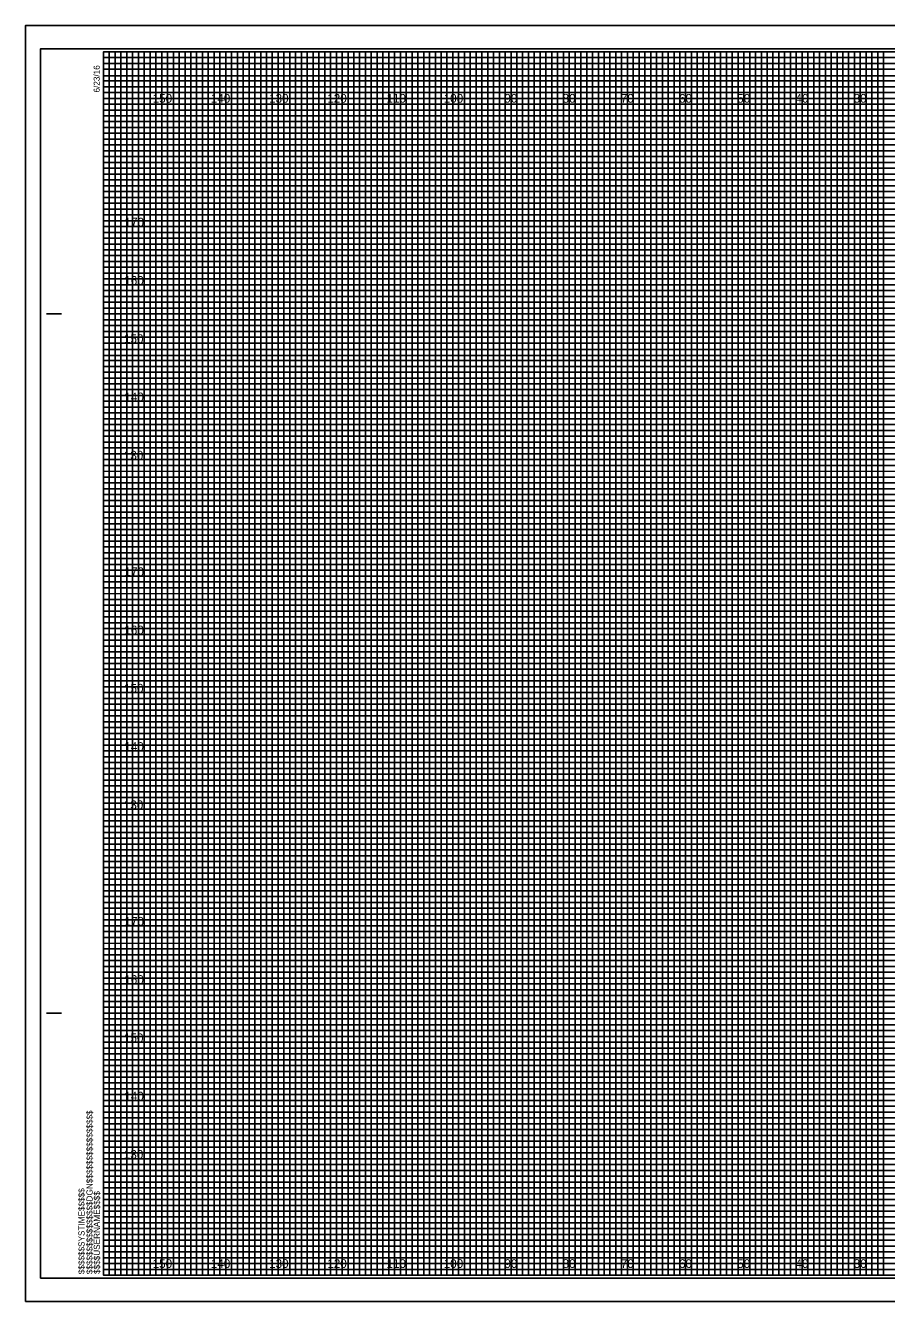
# Model space of a CAD drawing. Extents: x -13 to 323, y -5 to 4834.
# Drawn here: x -13.4 to 134.5, y 2855.5 to 3074.5 of the extents above; entities that cross this region are included whole.
import ezdxf

# ---------------------------------------------------------------- set-up
doc = ezdxf.new("R2010")
doc.units = 0
for name, color, linetype in [('Exist Cross Section Cell', 7, 'Continuous'), ('Exist XS Center Line Elevation Label', 7, 'Continuous'), ('Exist XS Ground Line', 7, 'Continuous'), ('Prop CMT Pvmt Course 1', 7, 'Continuous'), ('Prop CMT Pvmt Course 2', 7, 'Continuous'), ('Prop CMT Pvmt Course 3', 7, 'Continuous'), ('Prop CMT Pvmt Surface Shoulder', 7, 'Continuous'), ('Prop CMT Shld Paved Course 1', 7, 'Continuous'), ('Prop CMT Shld Paved Course 2', 7, 'Continuous'), ('Prop CMT Shld Paved Course 3', 7, 'Continuous'), ('Prop CMT Slope Grass', 7, 'Continuous')]:
    doc.layers.add(name, color=color, linetype=linetype)

msp = doc.modelspace()

# ---------------------------------------------------------------- linework, layer by layer
at = {"layer": 'Exist XS Center Line Elevation Label'}
for points in [[(0, 3070), (5, 3070), (5, 2860), (15, 2860), (15, 3070), (25, 3070), (25, 2860), (35, 2860), (35, 3070), (45, 3070), (45, 2860), (55, 2860), (55, 3070), (65, 3070), (65, 2860), (75, 2860), (75, 3070), (85, 3070), (85, 2860), (95, 2860), (95, 3070), (105, 3070), (105, 2860), (115, 2860), (115, 3070), (125, 3070), (125, 2860), (135, 2860)], [(0, 3065), (275, 3065)], [(0, 3045), (320, 3045), (320, 3055), (0, 3055)], [(0, 3025), (320, 3025), (320, 3035), (0, 3035)], [(0, 3005), (320, 3005), (320, 3015), (0, 3015)], [(0, 2985), (320, 2985), (320, 2995), (0, 2995)], [(0, 2965), (320, 2965), (320, 2975), (0, 2975)], [(0, 2945), (320, 2945), (320, 2955), (0, 2955)], [(0, 2925), (320, 2925), (320, 2935), (0, 2935)], [(0, 2905), (320, 2905), (320, 2915), (0, 2915)], [(0, 2885), (320, 2885), (320, 2895), (0, 2895)], [(0, 2865), (320, 2865), (320, 2875), (0, 2875)]]:
    msp.add_lwpolyline(points, dxfattribs=at)
at = {"layer": 'Exist XS Ground Line'}
for p, q in [((10, 3070), (0, 3070)), ((10, 2860), (10, 3070)), ((30, 3070), (20, 3070)), ((20, 3070), (20, 2860)), ((30, 2860), (30, 3070)), ((50, 3070), (40, 3070)), ((40, 3070), (40, 2860)), ((50, 2860), (50, 3070)), ((70, 3070), (60, 3070)), ((60, 3070), (60, 2860)), ((70, 2860), (70, 3070)), ((90, 3070), (80, 3070)), ((80, 3070), (80, 2860)), ((90, 2860), (90, 3070)), ((110, 3070), (100, 3070)), ((100, 3070), (100, 2860)), ((110, 2860), (110, 3070)), ((130, 3070), (120, 3070)), ((120, 3070), (120, 2860)), ((130, 2860), (130, 3070)), ((20, 2860), (10, 2860)), ((40, 2860), (30, 2860)), ((60, 2860), (50, 2860)), ((80, 2860), (70, 2860)), ((100, 2860), (90, 2860)), ((120, 2860), (110, 2860)), ((140, 2860), (130, 2860))]:
    msp.add_line(p, q, dxfattribs=at)
for points in [[(0, 3060), (320, 3060), (320, 3050), (0, 3050)], [(0, 3040), (320, 3040), (320, 3030), (0, 3030)], [(0, 3020), (320, 3020), (320, 3010), (0, 3010)], [(0, 3000), (320, 3000), (320, 2990), (0, 2990)], [(0, 2980), (320, 2980), (320, 2970), (0, 2970)], [(0, 2960), (320, 2960), (320, 2950), (0, 2950)], [(0, 2940), (320, 2940), (320, 2930), (0, 2930)], [(0, 2920), (320, 2920), (320, 2910), (0, 2910)], [(0, 2900), (320, 2900), (320, 2890), (0, 2890)], [(0, 2880), (320, 2880), (320, 2870), (0, 2870)]]:
    msp.add_lwpolyline(points, dxfattribs=at)
at = {"layer": 'Prop CMT Pvmt Course 1'}
for points in [[(0, 2860), (1, 2860), (1, 3070), (2, 3070), (2, 2860)], [(2, 2860), (3, 2860), (3, 3070), (4, 3070), (4, 2860)], [(5, 2860), (6, 2860), (6, 3070), (7, 3070), (7, 2860)], [(7, 2860), (8, 2860), (8, 3070), (9, 3070), (9, 2860)], [(10, 2860), (11, 2860), (11, 3070), (12, 3070), (12, 2860)], [(12, 2860), (13, 2860), (13, 3070), (14, 3070), (14, 2860)], [(15, 2860), (16, 2860), (16, 3070), (17, 3070), (17, 2860)], [(17, 2860), (18, 2860), (18, 3070), (19, 3070), (19, 2860)], [(20, 2860), (21, 2860), (21, 3070), (22, 3070), (22, 2860)], [(22, 2860), (23, 2860), (23, 3070), (24, 3070), (24, 2860)], [(25, 2860), (26, 2860), (26, 3070), (27, 3070), (27, 2860)], [(27, 2860), (28, 2860), (28, 3070), (29, 3070), (29, 2860)], [(30, 2860), (31, 2860), (31, 3070), (32, 3070), (32, 2860)], [(32, 2860), (33, 2860), (33, 3070), (34, 3070), (34, 2860)], [(35, 2860), (36, 2860), (36, 3070), (37, 3070), (37, 2860)], [(37, 2860), (38, 2860), (38, 3070), (39, 3070), (39, 2860)], [(40, 2860), (41, 2860), (41, 3070), (42, 3070), (42, 2860)], [(42, 2860), (43, 2860), (43, 3070), (44, 3070), (44, 2860)], [(45, 2860), (46, 2860), (46, 3070), (47, 3070), (47, 2860)], [(47, 2860), (48, 2860), (48, 3070), (49, 3070), (49, 2860)], [(50, 2860), (51, 2860), (51, 3070), (52, 3070), (52, 2860)], [(52, 2860), (53, 2860), (53, 3070), (54, 3070), (54, 2860)], [(55, 2860), (56, 2860), (56, 3070), (57, 3070), (57, 2860)], [(57, 2860), (58, 2860), (58, 3070), (59, 3070), (59, 2860)], [(60, 2860), (61, 2860), (61, 3070), (62, 3070), (62, 2860)], [(62, 2860), (63, 2860), (63, 3070), (64, 3070), (64, 2860)], [(65, 2860), (66, 2860), (66, 3070), (67, 3070), (67, 2860)], [(67, 2860), (68, 2860), (68, 3070), (69, 3070), (69, 2860)], [(70, 2860), (71, 2860), (71, 3070), (72, 3070), (72, 2860)], [(72, 2860), (73, 2860), (73, 3070), (74, 3070), (74, 2860)], [(75, 2860), (76, 2860), (76, 3070), (77, 3070), (77, 2860)], [(77, 2860), (78, 2860), (78, 3070), (79, 3070), (79, 2860)], [(80, 2860), (81, 2860), (81, 3070), (82, 3070), (82, 2860)], [(82, 2860), (83, 2860), (83, 3070), (84, 3070), (84, 2860)], [(85, 2860), (86, 2860), (86, 3070), (87, 3070), (87, 2860)], [(87, 2860), (88, 2860), (88, 3070), (89, 3070), (89, 2860)], [(90, 2860), (91, 2860), (91, 3070), (92, 3070), (92, 2860)], [(92, 2860), (93, 2860), (93, 3070), (94, 3070), (94, 2860)], [(95, 2860), (96, 2860), (96, 3070), (97, 3070), (97, 2860)], [(97, 2860), (98, 2860), (98, 3070), (99, 3070), (99, 2860)], [(100, 2860), (101, 2860), (101, 3070), (102, 3070), (102, 2860)], [(102, 2860), (103, 2860), (103, 3070), (104, 3070), (104, 2860)], [(105, 2860), (106, 2860), (106, 3070), (107, 3070), (107, 2860)], [(107, 2860), (108, 2860), (108, 3070), (109, 3070), (109, 2860)], [(110, 2860), (111, 2860), (111, 3070), (112, 3070), (112, 2860)], [(112, 2860), (113, 2860), (113, 3070), (114, 3070), (114, 2860)], [(115, 2860), (116, 2860), (116, 3070), (117, 3070), (117, 2860)], [(117, 2860), (118, 2860), (118, 3070), (119, 3070), (119, 2860)], [(120, 2860), (121, 2860), (121, 3070), (122, 3070), (122, 2860)], [(122, 2860), (123, 2860), (123, 3070), (124, 3070), (124, 2860)], [(125, 2860), (126, 2860), (126, 3070), (127, 3070), (127, 2860)], [(127, 2860), (128, 2860), (128, 3070), (129, 3070), (129, 2860)], [(130, 2860), (131, 2860), (131, 3070), (132, 3070), (132, 2860)], [(132, 2860), (133, 2860), (133, 3070), (134, 3070), (134, 2860)]]:
    msp.add_lwpolyline(points, dxfattribs=at)
at = {"layer": 'Prop CMT Pvmt Course 2'}
for p, q in [((323.3, 3074.5), (-13.4, 3074.5)), ((-13.4, 3074.5), (-13.4, 2855.5)), ((-13.4, 2855.5), (323.3, 2855.5))]:
    msp.add_line(p, q, dxfattribs=at)
at = {"layer": 'Prop CMT Pvmt Surface Shoulder'}
for p, q in [((-9.8, 3025), (-7.3, 3025)), ((-9.7, 3025), (-7.2, 3025)), ((-9.8, 2905), (-7.3, 2905)), ((-9.7, 2905), (-7.2, 2905)), ((0, 2860), (0, 2860)), ((0, 2860), (0, 2860)), ((0, 2860), (0, 2860)), ((0, 2860), (0, 2860)), ((0, 2860), (0, 2860)), ((0, 2860), (0, 2860)), ((0, 2860), (0, 2860))]:
    msp.add_line(p, q, dxfattribs=at)
msp.add_lwpolyline([(320, 3070), (0, 3070), (0, 2860), (320, 2860)], close=True, dxfattribs=at)
at = {"layer": 'Prop CMT Shld Paved Course 1'}
msp.add_lwpolyline([(-13.4, 2855.5), (323.3, 2855.5), (323.3, 3074.5), (-13.4, 3074.5)], close=True, dxfattribs=at)
at = {"layer": 'Prop CMT Shld Paved Course 2'}
msp.add_lwpolyline([(-10.8, 2859.5), (322.4, 2859.5), (322.4, 3070.5), (-10.8, 3070.5)], close=True, dxfattribs=at)
at = {"layer": 'Prop CMT Shld Paved Course 3'}
for p, q in [((10, 2860), (10, 3070)), ((20, 2860), (20, 3070)), ((30, 2860), (30, 3070)), ((40, 2860), (40, 3070)), ((50, 2860), (50, 3070)), ((60, 2860), (60, 3070)), ((70, 2860), (70, 3070)), ((80, 2860), (80, 3070)), ((90, 2860), (90, 3070)), ((100, 2860), (100, 3070)), ((110, 2860), (110, 3070)), ((120, 2860), (120, 3070)), ((130, 2860), (130, 3070)), ((0, 3060), (320, 3060)), ((0, 3050), (320, 3050)), ((0, 3040), (320, 3040)), ((0, 3030), (320, 3030)), ((0, 3020), (320, 3020)), ((0, 3010), (320, 3010)), ((0, 3000), (320, 3000)), ((0, 2990), (320, 2990)), ((0, 2980), (320, 2980)), ((0, 2970), (320, 2970)), ((0, 2960), (320, 2960)), ((0, 2950), (320, 2950)), ((0, 2940), (320, 2940)), ((0, 2930), (320, 2930)), ((0, 2920), (320, 2920)), ((0, 2910), (320, 2910)), ((0, 2900), (320, 2900)), ((0, 2890), (320, 2890)), ((0, 2880), (320, 2880)), ((0, 2870), (320, 2870))]:
    msp.add_line(p, q, dxfattribs=at)
at = {"layer": 'Prop CMT Slope Grass'}
for p, q in [((0, 3069), (260, 3069)), ((260, 3067.98), (0, 3067.98)), ((0, 3067.98), (0, 3067)), ((0, 3067), (260, 3067)), ((260, 3065.89), (0, 3065.89)), ((0, 3065.89), (0, 3064)), ((0, 3064), (320, 3064))]:
    msp.add_line(p, q, dxfattribs=at)
for points in [[(0, 3063), (270, 3063), (320, 3063), (320, 3062), (0, 3062)], [(0, 3061), (320, 3061), (320, 3059), (0, 3059)], [(0, 3058), (320, 3058), (320, 3057), (0, 3056.98)], [(0, 3056), (320, 3056), (320, 3054), (0, 3054)], [(0, 3053), (320, 3053), (320, 3052), (0, 3052)], [(0, 3051), (320, 3051), (320, 3049), (0, 3049)], [(0, 3048), (320, 3048), (320, 3047), (0, 3047)], [(0, 3046), (320, 3046), (320, 3044), (0, 3044)], [(0, 3043), (320, 3043), (320, 3042), (0, 3042)], [(0, 3041), (320, 3041), (320, 3039), (0, 3039)], [(0, 3038), (320, 3038), (320, 3037), (0, 3037)], [(0, 3036), (320, 3036), (320, 3033.95), (320, 3033), (320, 3032), (0, 3032)], [(0, 3034), (320, 3034), (320, 3033), (0, 3033)], [(0, 3031), (320, 3031), (320, 3029), (0, 3029.03)], [(0, 3029.03), (320, 3029), (320, 3028), (0, 3028)], [(0, 3027), (320, 3027), (320, 3026), (0, 3026)], [(0, 3024), (320, 3024), (320, 3023), (0, 3023)], [(0, 3022), (320, 3022), (320, 3021), (0, 3021)], [(-0.07, 3018.89), (320, 3018.89), (320, 3017.88), (-0.07, 3017.88)], [(0, 3017), (320, 3017), (320, 3016), (0, 3016)], [(0, 3014), (320, 3014), (320, 3013), (0, 3013)], [(0, 3012), (320, 3012), (320, 3011), (0, 3011)], [(0, 3009), (320, 3009), (320, 3008), (0, 3008)], [(0, 3007), (320, 3007), (320, 3006), (0, 3006)], [(0, 3004), (320, 3004), (320, 3003), (0, 3003)], [(0, 3002), (320, 3002), (320, 3001), (0, 3001)], [(0, 2999), (320, 2999), (319.99, 2997.98), (0, 2998)], [(0, 2997), (320, 2997), (320, 2996), (0, 2996)], [(0, 2994), (320, 2994), (320, 2993), (0, 2993)], [(0, 2992), (320, 2992), (320, 2991), (0, 2991)], [(0, 2989), (320, 2989), (320, 2988), (0, 2988)], [(0, 2987), (320, 2987), (320, 2986), (0, 2986)], [(0, 2984), (320, 2984), (320, 2983), (0, 2983)], [(0, 2982), (320, 2982), (320, 2981), (0, 2981)], [(0, 2979), (320, 2979), (320, 2978), (0, 2978)], [(0, 2976.99), (320.07, 2976.91), (320, 2976), (0, 2976)], [(0, 2974), (320, 2974), (320, 2973), (0, 2973)], [(0, 2972), (320, 2972), (320, 2971), (0, 2971)], [(0, 2969), (320, 2969), (320, 2968), (0, 2968)], [(0, 2967), (320, 2967), (320, 2966), (0, 2966)], [(0, 2964), (320, 2964), (320, 2963), (0, 2963)], [(0, 2962), (320, 2962), (320, 2961), (0, 2961)], [(0, 2959), (320, 2959), (320, 2958), (0, 2958)], [(0, 2957), (320, 2957), (320, 2956), (0, 2956)], [(0, 2954), (320, 2954), (320, 2953), (0, 2953)], [(0, 2952), (320, 2952), (320, 2951), (0, 2951)], [(0, 2949), (320, 2949), (320, 2948), (0, 2948)], [(0, 2947), (320, 2947), (320, 2946), (0, 2946)], [(0, 2944), (320, 2944), (320, 2943), (0, 2943)], [(0, 2942), (320, 2942), (320, 2941), (0, 2941)], [(0, 2939), (320, 2939), (319.99, 2937.98), (0, 2938)], [(0, 2937), (320, 2937), (320, 2936), (0, 2936)], [(0, 2934), (320, 2934), (320, 2933), (0, 2933)], [(0, 2932), (320, 2932), (320, 2931), (0, 2931)], [(0, 2929), (320, 2929), (320, 2928), (0, 2928)], [(0, 2927), (320, 2927), (320, 2926), (0, 2926)], [(0, 2924), (320, 2924), (320, 2923), (0, 2923)], [(0, 2922), (320, 2922), (320, 2921), (0, 2921)], [(0, 2919), (320, 2919), (320, 2918), (0, 2918)], [(0, 2916.99), (320.07, 2916.91), (320, 2916), (0, 2916)], [(0, 2914), (320, 2914), (320, 2913), (0, 2913)], [(0, 2912), (320, 2912), (320, 2911), (0, 2911)], [(0, 2909), (320, 2909), (320, 2908), (0, 2908)], [(0, 2907), (320, 2907), (320, 2906), (0, 2906)], [(0, 2904), (320, 2904), (320, 2903), (0, 2903)], [(0, 2902), (320, 2902), (320, 2901), (0, 2901)], [(0, 2899), (320, 2899), (320, 2898), (0, 2898)], [(0, 2897), (320, 2897), (320, 2896), (0, 2896)], [(0, 2894), (320, 2894), (320, 2893), (0, 2893)], [(0, 2892), (320, 2892), (320, 2891), (0, 2891)], [(0, 2889), (320, 2889), (320, 2888), (0, 2888)], [(0, 2887), (320, 2887), (320, 2886), (0, 2886)], [(0, 2884), (320, 2884), (320, 2883), (0, 2883)], [(0, 2882), (320, 2882), (320, 2881), (0, 2881)], [(0, 2879), (320, 2879), (320, 2878), (0, 2878)], [(0, 2877), (320, 2877), (320, 2876), (0, 2876)], [(0, 2874), (320, 2874), (320, 2873), (0, 2873)], [(0, 2872), (320, 2872), (320, 2871), (0, 2871)], [(0, 2869), (320, 2869), (320, 2868), (0, 2868)], [(0, 2867), (320, 2867), (320, 2866), (0, 2866)], [(0, 2864), (320, 2864), (320, 2863), (0, 2863)], [(0, 2862), (320, 2862), (320, 2861), (0, 2861)]]:
    msp.add_lwpolyline(points, dxfattribs=at)

# ---------------------------------------------------------------- texts
at = {"layer": 'Exist Cross Section Cell'}
for s, p in [('150', (8.44, 3061.25)), ('140', (18.44, 3061.25)), ('130', (28.44, 3061.25)), ('120', (38.44, 3061.25)), ('110', (48.62, 3061.25)), ('100', (58.44, 3061.25)), ('90', (68.86, 3061.25)), ('80', (78.86, 3061.25)), ('70', (88.86, 3061.25)), ('60', (98.86, 3061.25)), ('50', (108.86, 3061.25)), ('40', (118.86, 3061.25)), ('30', (128.86, 3061.25)), ('150', (8.44, 2861.25)), ('140', (18.44, 2861.25)), ('130', (28.44, 2861.25)), ('120', (38.44, 2861.25)), ('110', (48.62, 2861.25)), ('100', (58.44, 2861.25)), ('90', (68.86, 2861.25)), ('80', (78.86, 2861.25)), ('70', (88.86, 2861.25)), ('60', (98.86, 2861.25)), ('50', (108.86, 2861.25)), ('40', (118.86, 2861.25)), ('30', (128.86, 2861.25))]:
    msp.add_text(s, height=1.5, dxfattribs=at).set_placement(p)
at = {"layer": 'Prop CMT Pvmt Course 3'}
for s, p in [('170', (3.61, 3040)), ('160', (3.57, 3030)), ('150', (3.52, 3020)), ('140', (3.57, 3010)), ('130', (3.49, 3000)), ('170', (3.61, 2980)), ('160', (3.57, 2970)), ('150', (3.52, 2960)), ('140', (3.57, 2950)), ('130', (3.49, 2940)), ('170', (3.61, 2920)), ('160', (3.57, 2910)), ('150', (3.52, 2900)), ('140', (3.57, 2890)), ('130', (3.49, 2880))]:
    msp.add_text(s, height=1.5, dxfattribs=at).set_placement(p)
at = {"layer": 'Prop CMT Pvmt Surface Shoulder'}
for s, p in [('6/23/16', (-0.65, 3063)), ('$$$$$$$$$$$$$$$$DGN$$$$$$$$$$$$$$$$', (-1.88, 2860.18)), ('$$$$$$SYSTIME$$$$$', (-3.26, 2860.18)), ('$$$$USERNAME$$$$', (-0.62, 2860.23))]:
    msp.add_text(s, height=1.05, rotation=90, dxfattribs=at).set_placement(p)

doc.saveas('drawing.dxf')
